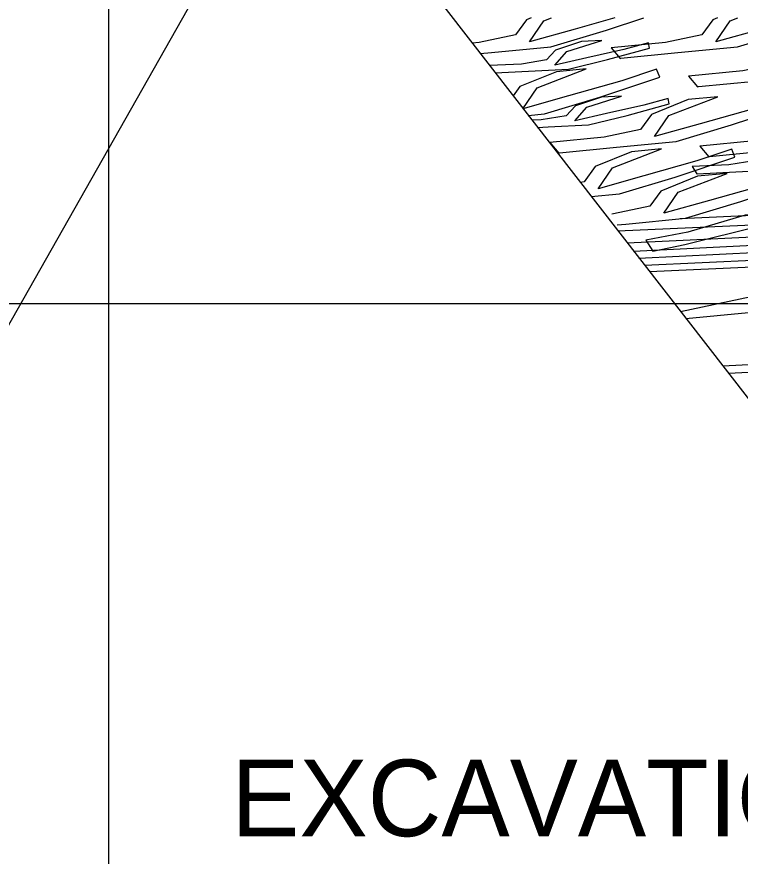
# Model space of a CAD drawing. Extents: x 1578769 to 1579225, y 724002 to 724828.
# Drawn here: x 1578873.59 to 1578878.33, y 724309.54 to 724315.03 of the extents above; entities that cross this region are included whole.
import ezdxf

# ---------------------------------------------------------------- set-up
doc = ezdxf.new("R2010")
doc.units = 0
for name, color, linetype in [('1', 7, 'Continuous'), ('G-ANNO-SYMB', 7, 'Continuous'), ('Old_Level_1', 7, 'Continuous'), ('Old_Level_41', 7, 'Continuous'), ('R_Fin Surface', 7, 'Continuous')]:
    doc.layers.add(name, color=color, linetype=linetype)

msp = doc.modelspace()

# ---------------------------------------------------------------- linework, layer by layer
at = {"layer": '1'}
msp.add_lwpolyline([(1578874.8171, 724315.2669), (1578872.6013, 724311.3582), (1578871.916, 724311.3582)], dxfattribs=at)
at = {"layer": 'G-ANNO-SYMB'}
for points in [[(1578876.9569, 724315.0198), (1578876.9271, 724315.0077), (1578876.855, 724314.9089), (1578876.6172, 724314.8583), (1578876.5714, 724314.8539)], [(1578876.6253, 724314.7856), (1578876.6977, 724314.7926), (1578877.0876, 724314.8303), (1578877.4502, 724314.9388), (1578877.6944, 724315.0198)], [(1578877.5052, 724315.0198), (1578877.2449, 724314.9465), (1578876.9465, 724314.8626), (1578877.0403, 724315.0003), (1578877.0911, 724315.0198)], [(1578878.1757, 724315.0198), (1578878.146, 724315.0077), (1578878.0739, 724314.9089), (1578877.836, 724314.8583), (1578877.4804, 724314.824)], [(1578877.4804, 724314.824), (1578877.5389, 724314.755), (1578877.5444, 724314.7567), (1578877.9166, 724314.7926), (1578878.3065, 724314.8303), (1578878.669, 724314.9388), (1578878.9132, 724315.0198)], [(1578878.7241, 724315.0198), (1578878.4638, 724314.9465), (1578878.1653, 724314.8626), (1578878.2592, 724315.0003), (1578878.31, 724315.0198)], [(1578877.9873, 724314.6381), (1578878.0458, 724314.5691), (1578878.0513, 724314.5708), (1578878.4235, 724314.6068), (1578878.8134, 724314.6444), (1578879.1759, 724314.753), (1578879.5671, 724314.8826), (1578879.5465, 724314.9358), (1578879.3189, 724314.8587), (1578878.9707, 724314.7607), (1578878.6722, 724314.6767), (1578878.7661, 724314.8144), (1578879.0863, 724314.9373), (1578878.8914, 724314.9184), (1578878.6529, 724314.8219), (1578878.5808, 724314.723), (1578878.3429, 724314.6725), (1578877.9873, 724314.6381)], [(1578876.7222, 724314.6608), (1578876.9397, 724314.6719), (1578877.2031, 724314.6853), (1578877.4567, 724314.7465), (1578877.7319, 724314.8209), (1578877.7246, 724314.8568), (1578877.5643, 724314.8124), (1578877.3214, 724314.7578), (1578877.1132, 724314.7109), (1578877.192, 724314.7996), (1578877.4192, 724314.8716), (1578877.2876, 724314.8649), (1578877.1177, 724314.8079), (1578877.058, 724314.7444), (1578876.894, 724314.7179), (1578876.6861, 724314.7074)], [(1578876.9385, 724314.3825), (1578877.0451, 724314.3928), (1578877.4076, 724314.5013), (1578877.7987, 724314.631), (1578877.7782, 724314.6841), (1578877.5506, 724314.607), (1578877.2024, 724314.509), (1578876.9039, 724314.4251), (1578876.9978, 724314.5628), (1578877.318, 724314.6856), (1578877.123, 724314.6668), (1578876.8846, 724314.5702), (1578876.8401, 724314.5092)], [(1578876.9993, 724314.3042), (1578877.0691, 724314.3078), (1578877.3325, 724314.3211), (1578877.5862, 724314.3824), (1578877.8614, 724314.4568), (1578877.8541, 724314.4927), (1578877.6938, 724314.4483), (1578877.4509, 724314.3937), (1578877.2427, 724314.3468), (1578877.3214, 724314.4354), (1578877.5487, 724314.5074), (1578877.417, 724314.5007), (1578877.2472, 724314.4438), (1578877.1875, 724314.3803), (1578877.0235, 724314.3538), (1578876.9632, 724314.3507)], [(1578877.0798, 724314.2053), (1578877.1383, 724314.1363), (1578877.1438, 724314.138), (1578877.516, 724314.1739), (1578877.9059, 724314.2116), (1578878.2684, 724314.3201), (1578878.6596, 724314.4498), (1578878.639, 724314.5029), (1578878.4114, 724314.4258), (1578878.0632, 724314.3279), (1578877.7647, 724314.2439), (1578877.8586, 724314.3816), (1578878.1788, 724314.5044), (1578877.9839, 724314.4856), (1578877.7454, 724314.389), (1578877.6733, 724314.2902), (1578877.4354, 724314.2396), (1578877.0798, 724314.2053)], [(1578878.0608, 724314.1813), (1578878.1194, 724314.1122), (1578878.1248, 724314.1139), (1578878.497, 724314.1499), (1578878.8869, 724314.1875), (1578879.2495, 724314.2961), (1578879.6406, 724314.4257), (1578879.6201, 724314.4789), (1578879.3925, 724314.4018), (1578879.0442, 724314.3038), (1578878.7457, 724314.2198), (1578878.8396, 724314.3576), (1578879.1598, 724314.4804), (1578878.9649, 724314.4615), (1578878.7264, 724314.365), (1578878.6543, 724314.2661), (1578878.4164, 724314.2156), (1578878.0608, 724314.1813)], [(1578878.0099, 724314.0473), (1578878.0405, 724313.9998), (1578878.0443, 724314.0007), (1578878.2958, 724314.0135), (1578878.5592, 724314.0269), (1578878.8128, 724314.0881), (1578879.088, 724314.1626), (1578879.0807, 724314.1985), (1578878.9204, 724314.154), (1578878.6775, 724314.0994), (1578878.4693, 724314.0525), (1578878.548, 724314.1412), (1578878.7753, 724314.2132), (1578878.6436, 724314.2065), (1578878.4738, 724314.1495), (1578878.4141, 724314.086), (1578878.2501, 724314.0595), (1578878.0099, 724314.0473)], [(1578877.3506, 724313.8521), (1578877.5365, 724313.8701), (1578877.899, 724313.9786), (1578878.2902, 724314.1083), (1578878.2696, 724314.1614), (1578878.042, 724314.0843), (1578877.6938, 724313.9863), (1578877.3953, 724313.9024), (1578877.4892, 724314.0401), (1578877.8094, 724314.1629), (1578877.6145, 724314.1441), (1578877.376, 724314.0475), (1578877.3039, 724313.9487), (1578877.2796, 724313.9435)], [(1578877.521, 724313.6671), (1578877.5773, 724313.6725), (1578877.9672, 724313.7102), (1578878.3298, 724313.8187), (1578878.7209, 724313.9484), (1578878.7004, 724314.0015), (1578878.4728, 724313.9244), (1578878.1245, 724313.8264), (1578877.826, 724313.7425), (1578877.9199, 724313.8802), (1578878.2402, 724314.003), (1578878.0452, 724313.9842), (1578877.8067, 724313.8876), (1578877.7346, 724313.7888), (1578877.4968, 724313.7382), (1578877.4856, 724313.7371)], [(1578877.7074, 724313.5678), (1578877.7536, 724313.4961), (1578877.962, 724313.5376), (1578878.4627, 724313.6628), (1578878.8399, 724313.682), (1578879.235, 724313.702), (1578879.6155, 724313.7939), (1578880.0283, 724313.9055), (1578880.0173, 724313.9594), (1578879.7768, 724313.8928), (1578879.4125, 724313.8108), (1578879.1001, 724313.7405), (1578879.2183, 724313.8735), (1578879.5592, 724313.9815), (1578879.3617, 724313.9714), (1578879.1069, 724313.8859), (1578879.0174, 724313.7907), (1578878.7714, 724313.751), (1578878.3584, 724313.73), (1578877.9815, 724313.6202), (1578877.7074, 724313.5678)], [(1578877.9697, 724313.0554), (1578878.6291, 724313.1191), (1578878.9916, 724313.2276), (1578879.3828, 724313.3573), (1578879.3622, 724313.4104), (1578879.1346, 724313.3333), (1578878.7864, 724313.2354), (1578878.4879, 724313.1514), (1578878.5818, 724313.2891), (1578878.902, 724313.4119), (1578878.7071, 724313.3931), (1578878.4686, 724313.2965), (1578878.3965, 724313.1977), (1578877.9353, 724313.0997)], [(1578878.2476, 724312.6977), (1578878.5103, 724312.711), (1578878.7737, 724312.7244), (1578879.0274, 724312.7856), (1578879.3025, 724312.8601), (1578879.2952, 724312.896), (1578879.1349, 724312.8515), (1578878.892, 724312.7969), (1578878.6838, 724312.75), (1578878.7626, 724312.8387), (1578878.9899, 724312.9107), (1578878.8582, 724312.904), (1578878.6883, 724312.847), (1578878.6286, 724312.7835), (1578878.4646, 724312.7571), (1578878.2115, 724312.7442)]]:
    msp.add_lwpolyline(points, dxfattribs=at)
at = {"layer": 'Old_Level_1'}
for p, q in [((1578877.9316, 724313.7087), (1578881.0834, 724313.8533)), ((1578877.5251, 724313.6276), (1578879.6145, 724313.7239)), ((1578877.5854, 724313.55), (1578881.0709, 724313.7134)), ((1578877.628, 724313.4951), (1578879.2253, 724313.5734)), ((1578877.6991, 724313.4036), (1578881.0041, 724313.5565)), ((1578877.6628, 724313.4503), (1578879.5002, 724313.5376)), ((1578877.7309, 724313.3627), (1578880.978, 724313.5119))]:
    msp.add_line(p, q, dxfattribs=at)
at = {"layer": 'Old_Level_41'}
msp.add_line((1578874.1939, 724333.1501), (1578874.1939, 724303.1501), dxfattribs=at)
msp.add_lwpolyline([(1578924.1939, 724313.1501), (1578824.1939, 724313.1501)], dxfattribs=at)
at = {"layer": 'R_Fin Surface'}
msp.add_lwpolyline([(1578875.4555, 724316.0932), (1578876.4018, 724315.0732), (1578878.6731, 724312.1501)], dxfattribs=at)
msp.add_lwpolyline([(1578875.4555, 724316.0932), (1578876.4018, 724315.0732), (1578878.6731, 724312.1501)], dxfattribs=at)

# ---------------------------------------------------------------- texts
at = {"layer": '1'}
msp.add_text('EXCAVATION LINE', height=0.5, dxfattribs=at).set_placement((1578874.9968, 724309.6722))

doc.saveas('drawing.dxf')
